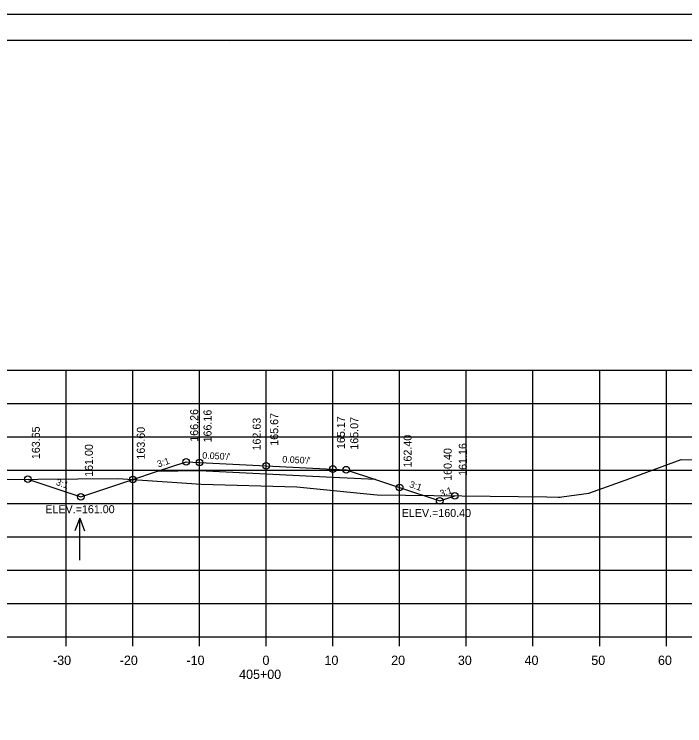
# Model space of a CAD drawing. Extents: x 1368503 to 1373085, y 379840 to 381833.
# Drawn here: x 1372884.3 to 1372984.8, y 380495 to 380601.6 of the extents above; entities that cross this region are included whole.
import ezdxf

# ---------------------------------------------------------------- set-up
doc = ezdxf.new("R2010")
doc.units = 0
for name, color, linetype in [('S_BRIDGE', 7, 'Continuous'), ('S_EDGE_PAVEMENT', 7, 'Continuous'), ('S_GRAVEL_ROAD', 7, 'Continuous'), ('S_MISC_BOUNDARY', 7, 'Continuous'), ('S_OBSCURES', 7, 'Continuous'), ('S_PHOTO_CENTERS', 7, 'Continuous'), ('S_PHOTO_NOTES', 7, 'Continuous'), ('S_RDW_PT_SYM', 7, 'Continuous'), ('S_SHOULDER', 7, 'Continuous'), ('S_STREAM_ANNOT', 7, 'Continuous'), ('S_TRAILS', 7, 'Continuous'), ('S_TRAILS_ANNOT', 7, 'Continuous')]:
    doc.layers.add(name, color=color, linetype=linetype)

msp = doc.modelspace()

# ---------------------------------------------------------------- linework, layer by layer
at = {"layer": 'S_BRIDGE'}
for p, q in [((1372764.08, 380597.75), (1373080.26, 380597.75)), ((1372916.6, 380597.49), (1372916.6, 380597.49)), ((1372916.6, 380597.49), (1372916.6, 380597.49))]:
    msp.add_line(p, q, dxfattribs=at)
at = {"layer": 'S_EDGE_PAVEMENT'}
for p, q in [((1372782.08, 380508.29), (1373062.08, 380508.29)), ((1372892.08, 380506.89), (1372892.08, 380508.29)), ((1372902.08, 380506.89), (1372902.08, 380508.29)), ((1372912.08, 380506.89), (1372912.08, 380508.29)), ((1372922.08, 380506.89), (1372922.08, 380508.29)), ((1372932.08, 380506.89), (1372932.08, 380508.29)), ((1372942.08, 380506.89), (1372942.08, 380508.29)), ((1372952.08, 380506.89), (1372952.08, 380508.29)), ((1372962.08, 380506.89), (1372962.08, 380508.29)), ((1372972.08, 380506.89), (1372972.08, 380508.29)), ((1372982.08, 380506.89), (1372982.08, 380508.29))]:
    msp.add_line(p, q, dxfattribs=at)
at = {"layer": 'S_GRAVEL_ROAD'}
for p, q in [((1372894.11, 380526.1), (1372893.41, 380524.18)), ((1372894.11, 380519.82), (1372894.11, 380526.1)), ((1372894.11, 380526.1), (1372894.81, 380524.18))]:
    msp.add_line(p, q, dxfattribs=at)
at = {"layer": 'S_MISC_BOUNDARY'}
msp.add_lwpolyline([(1372882.35, 380531.9), (1372887.83, 380531.95), (1372899.82, 380532.03), (1372907.25, 380531.52), (1372912.34, 380531.21), (1372926.67, 380530.79), (1372938.15, 380529.64), (1372938.73, 380529.58), (1372964.15, 380529.28), (1372965.83, 380529.26), (1372966.15, 380529.23), (1372966.41, 380529.27), (1372970.45, 380529.86), (1372976.59, 380532.06), (1372977.23, 380532.29), (1372978.2, 380532.64), (1372984.28, 380534.9), (1372986.19, 380534.85)], dxfattribs=at)
at = {"layer": 'S_OBSCURES'}
msp.add_lwpolyline([(1372938.49, 380531.89), (1372932.08, 380532.21), (1372922.08, 380532.7), (1372912.08, 380533.2), (1372905.65, 380533.07)], dxfattribs=at)
at = {"layer": 'S_PHOTO_CENTERS'}
for p, q in [((1372782.08, 380548.29), (1373062.08, 380548.29)), ((1372892.08, 380508.29), (1372892.08, 380548.29)), ((1372902.08, 380508.29), (1372902.08, 380548.29)), ((1372912.08, 380508.29), (1372912.08, 380548.29)), ((1372922.08, 380508.29), (1372922.08, 380548.29)), ((1372932.08, 380508.29), (1372932.08, 380548.29)), ((1372942.08, 380508.29), (1372942.08, 380548.29)), ((1372952.08, 380508.29), (1372952.08, 380548.29)), ((1372962.08, 380508.29), (1372962.08, 380548.29)), ((1372972.08, 380508.29), (1372972.08, 380548.29)), ((1372982.08, 380508.29), (1372982.08, 380548.29)), ((1372782.08, 380543.29), (1373062.08, 380543.29)), ((1372782.08, 380538.29), (1373062.08, 380538.29)), ((1372782.08, 380533.29), (1373062.08, 380533.29)), ((1372782.08, 380528.29), (1373062.08, 380528.29)), ((1372782.08, 380523.29), (1373062.08, 380523.29)), ((1372782.08, 380518.29), (1373062.08, 380518.29)), ((1372782.08, 380513.29), (1373062.08, 380513.29)), ((1372782.08, 380508.29), (1373062.08, 380508.29))]:
    msp.add_line(p, q, dxfattribs=at)
at = {"layer": 'S_PHOTO_NOTES'}
msp.add_line((1372751.68, 380601.64), (1373085.01, 380601.64), dxfattribs=at)
for points in [[(1372751.67, 380601.64), (1373085.01, 380601.64), (1373085.01, 380388.3), (1372751.67, 380388.3)], [(1372998, 380597.75), (1372998, 380587.87), (1373033.73, 380587.87), (1373033.73, 380584.95), (1373056.93, 380584.95), (1373056.93, 380560.61), (1373080.26, 380560.61), (1373080.26, 380392.29), (1372764.08, 380392.29), (1372764.08, 380597.75)]]:
    msp.add_lwpolyline(points, close=True, dxfattribs=at)
for centre in [(1372910.08, 380534.55), (1372912.08, 380534.45), (1372922.08, 380533.95), (1372932.08, 380533.46), (1372934.08, 380533.36), (1372886.34, 380531.94), (1372902.08, 380531.88), (1372942.08, 380530.69), (1372894.29, 380529.29), (1372950.36, 380529.44), (1372948.09, 380528.69)]:
    msp.add_circle(centre, 0.5, dxfattribs=at)
at = {"layer": 'S_STREAM_ANNOT'}
msp.add_lwpolyline([(1372886.34, 380531.94), (1372894.29, 380529.29), (1372902.08, 380531.88), (1372905.65, 380533.07), (1372910.08, 380534.55), (1372912.08, 380534.45), (1372922.08, 380533.95), (1372932.08, 380533.46), (1372934.08, 380533.36), (1372938.49, 380531.89), (1372942.08, 380530.69), (1372948.09, 380528.69), (1372950.36, 380529.44)], dxfattribs=at)

# ---------------------------------------------------------------- texts
at = {"layer": 'S_GRAVEL_ROAD'}
for s, p in [('ELEV.=161.00', (1372888.96, 380526.84)), ('ELEV.=160.40', (1372942.4, 380526.27))]:
    msp.add_text(s, height=1.2, dxfattribs=at).set_placement(p)
at = {"layer": 'S_RDW_PT_SYM'}
for s, rotation, p in [("0.050'/'", 357.1587, (1372912.47, 380535.03)), ('3:1', 18.4349, (1372905.92, 380533.69)), ("0.050'/'", 357.1587, (1372924.47, 380534.44)), ('3:1', 341.5668, (1372890.48, 380531.09)), ('3:1', 341.5661, (1372943.45, 380530.76)), ('3:1', 18.4332, (1372948.3, 380529.27))]:
    msp.add_text(s, height=1, rotation=rotation, dxfattribs=at).set_placement(p)
at = {"layer": 'S_SHOULDER'}
for s, p in [('166.26', (1372911.88, 380537.55)), ('166.16', (1372913.88, 380537.45)), ('165.67', (1372923.88, 380536.95)), ('165.17', (1372933.88, 380536.46)), ('165.07', (1372935.88, 380536.36)), ('163.65', (1372888.14, 380534.94)), ('163.60', (1372903.88, 380534.88)), ('162.40', (1372943.88, 380533.69)), ('161.00', (1372896.09, 380532.29)), ('161.16', (1372952.16, 380532.44)), ('160.40', (1372949.89, 380531.69))]:
    msp.add_text(s, height=1.2, rotation=90, dxfattribs=at).set_placement(p)
at = {"layer": 'S_TRAILS'}
for s, p in [('-30', (1372890.12, 380504.09)), ('-20', (1372900.12, 380504.09)), ('-10', (1372910.12, 380504.09)), ('0', (1372921.52, 380504.09)), ('10', (1372930.82, 380504.09)), ('20', (1372940.82, 380504.09)), ('30', (1372950.82, 380504.09)), ('40', (1372960.82, 380504.09)), ('50', (1372970.82, 380504.09)), ('60', (1372980.82, 380504.09)), ('405+00', (1372918.02, 380501.99))]:
    msp.add_text(s, height=1.4, dxfattribs=at).set_placement(p)
at = {"layer": 'S_TRAILS_ANNOT'}
msp.add_text('162.63', height=1.2, rotation=90, dxfattribs=at).set_placement((1372921.25, 380536.24))

doc.saveas('drawing.dxf')
